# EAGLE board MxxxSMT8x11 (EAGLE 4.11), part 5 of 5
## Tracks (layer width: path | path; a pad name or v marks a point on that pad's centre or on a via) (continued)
T4  (via drill 0.61) (continued)
  Top 0.254: v196.85,149.61 197.87,149.61 E69.3 | E72.4 186.94,148.84 186.94,149.1 v187.96,149.1 188.21,149.35 189.48,150.62 v189.48,151.13 | E81.12 170.43,150.11 v171.45,150.11 173.74,150.11 E75.3 175.51,149.86 v176.53,149.86 | v158.75,153.67 157.23,153.67 155.19,151.64 155.19,147.57 157.23,147.57 E84.10 | v238,140.46 238,140.21 234.44,140.21 233.68,140.97 233.68,141.48 234.7,142.49 234.7,149.61 v233.68,149.61 232.66,149.61 E78.12 | v220.98,147.32 219.96,147.32 E65.10
  Bottom 0.254: v196.85,149.61 196.34,149.1 v187.96,149.1 187.71,149.1 177.29,149.1 v176.53,149.86 | v158.75,153.67 159.77,152.65 168.91,152.65 v171.45,150.11 | v238,140.46 239.27,141.73 242.57,141.73 U$12.T2 | v233.68,149.61 232.41,148.34 222,148.34 v220.98,147.32 220.73,147.57 219.96,147.57 219.96,148.59 217.17,151.38 216.92,151.38 215.9,152.4 210.57,152.4 210.31,152.15 194.06,152.15 193.04,151.13 v189.48,151.13
T5  (via drill 0.61)
  Top 0.254: v196.85,83.57 197.87,83.57 E90.3 | E93.4 186.94,82.8 186.94,83.06 v187.96,83.06 188.21,83.31 189.48,84.58 v189.48,85.09 | E102.12 170.43,84.07 v171.45,84.07 173.74,84.07 E96.3 175.51,83.82 v176.53,83.82 | v158.75,87.63 157.23,87.63 155.19,85.6 155.19,81.53 157.23,81.53 E105.10 | v238,74.42 238,74.17 234.44,74.17 233.68,74.93 233.68,75.44 234.7,76.45 234.7,83.57 v233.68,83.57 232.66,83.57 E99.12 | v220.98,81.28 219.96,81.28 E86.10
  Bottom 0.254: v196.85,83.57 196.34,83.06 v187.96,83.06 187.71,83.06 177.29,83.06 v176.53,83.82 | v158.75,87.63 159.77,86.61 168.91,86.61 v171.45,84.07 | v238,74.42 239.27,75.69 242.57,75.69 U$15.T2 | v233.68,83.57 232.41,82.3 222,82.3 v220.98,81.28 220.73,81.53 219.96,81.53 219.96,82.55 217.17,85.34 216.92,85.34 215.9,86.36 210.57,86.36 210.31,86.11 194.06,86.11 193.04,85.09 v189.48,85.09
T6  (via drill 0.61)
  Top 0.254: v196.85,17.53 197.87,17.53 E111.3 | E114.4 186.94,16.76 186.94,17.02 v187.96,17.02 188.21,17.27 189.48,18.54 v189.48,19.05 | E123.12 170.43,18.03 v171.45,18.03 173.74,18.03 E117.3 175.51,17.78 v176.53,17.78 | v158.75,21.59 157.23,21.59 155.19,19.56 155.19,15.49 157.23,15.49 E126.10 | v238,8.38 238,8.13 234.44,8.13 233.68,8.89 233.68,9.4 234.7,10.41 234.7,17.53 v233.68,17.53 232.66,17.53 E120.12 | v220.98,15.24 219.96,15.24 E107.10
  Bottom 0.254: v196.85,17.53 196.34,17.02 v187.96,17.02 187.71,17.02 177.29,17.02 v176.53,17.78 | v158.75,21.59 159.77,20.57 168.91,20.57 v171.45,18.03 | v238,8.38 239.27,9.65 242.57,9.65 U$18.T2 | v233.68,17.53 232.41,16.26 222,16.26 v220.98,15.24 220.73,15.49 219.96,15.49 219.96,16.51 217.17,19.3 216.92,19.3 215.9,20.32 210.57,20.32 210.31,20.07 194.06,20.07 193.04,19.05 v189.48,19.05
U1  (via drill 0.61)
  Top 0.254: v26.67,47.24 25.65,47.24 E3.10 | 14.73,53.34 13.97,54.1 U$1.U1 | 14.73,53.34 v20.07,48.01 | v100.33,43.43 99.31,43.43 E21.13 | v95.25,47.75 94.23,47.75 94.23,48.01 E18.6 | v53.09,52.83 53.09,44.7 52.32,44.7 E9.12 | v107.19,45.97 107.7,46.48 107.7,50.29 v98.55,59.44 | v64.26,59.44 62.48,57.66 R1.2 | 14.73,53.34 v18.54,57.15
  Bottom 0.254: v26.67,47.24 25.91,48.01 v20.07,48.01 | v95.25,47.75 96.01,47.75 v100.33,43.43 100.58,43.69 102.87,45.97 v107.19,45.97 | v53.09,52.83 57.15,56.9 60.45,56.9 R2.1 61.47,56.9 61.72,56.9 R1.2 | v98.55,59.44 97.03,60.96 75.18,60.96 73.66,59.44 v64.26,59.44 64.01,59.18 51.31,59.18 49.28,57.15 v18.54,57.15
U2  (via drill 0.61)
  Top 0.254: v59.69,45.97 58.67,45.97 E9.4 | v68.58,46.48 69.6,46.48 69.6,46.74 E12.5 | v103.12,50.55 103.89,49.78 E21.7 | v93.22,52.32 87.88,46.99 E18.10 86.11,46.74 85.09,46.74 84.33,45.97 82.8,45.97 E15.4 81.03,45.72 v80.01,45.72 | 29.46,50.04 29.46,48.51 25.65,48.51 E3.9 | 29.46,50.04 30.73,51.31 35.56,51.31 | 35.56,51.31 36.07,51.31 36.07,48.77 36.58,48.26 E6.9 | 29.46,50.04 24.38,55.12 17.53,55.12 v17.53,54.86 | v49.02,45.72 48.26,46.48 48.26,49.78 38.86,59.18 35.56,59.18 35.56,51.31
  Bottom 0.254: v103.12,50.55 100.33,53.34 94.23,53.34 v93.22,52.32 | v80.01,45.72 69.34,45.72 68.83,46.23 v68.58,46.48 60.2,46.48 v59.69,45.97 59.44,45.72 v49.02,45.72 | v17.53,54.86 13.97,54.86 U$1.U2
U3  (via drill 0.61)
  Top 0.254: v59.69,112.01 58.67,112.01 E27.4 | v68.58,112.52 69.6,112.52 69.6,112.78 E30.5 | v103.12,116.59 103.89,115.82 E42.7 | v93.22,118.36 87.88,113.03 E39.10 86.11,112.78 85.09,112.78 84.33,112.01 82.8,112.01 E33.4 81.03,111.76 v80.01,111.76 | 29.46,116.08 29.46,114.55 25.65,114.55 E36.9 | 29.46,116.08 30.73,117.35 35.56,117.35 | 35.56,117.35 36.07,117.35 36.07,114.81 36.58,114.3 E23.9 | 29.46,116.08 24.38,121.16 17.53,121.16 v17.53,120.9 | v49.02,111.76 48.26,112.52 48.26,115.82 38.86,125.22 35.56,125.22 35.56,117.35
  Bottom 0.254: v103.12,116.59 100.33,119.38 94.23,119.38 v93.22,118.36 | v80.01,111.76 69.34,111.76 68.83,112.27 v68.58,112.52 60.2,112.52 v59.69,112.01 59.44,111.76 v49.02,111.76 | v17.53,120.9 13.97,120.9 U$6.U2
U4  (via drill 0.61)
  Top 0.254: v26.67,113.28 25.65,113.28 E36.10 | 14.73,119.38 13.97,120.14 U$6.U1 | 14.73,119.38 v20.07,114.05 | v100.33,109.47 99.31,109.47 E42.13 | v95.25,113.79 94.23,113.79 94.23,114.05 E39.6 | v53.09,118.87 53.09,110.74 52.32,110.74 E27.12 | v107.19,112.01 107.7,112.52 107.7,116.33 v98.55,125.48 | v64.26,125.48 62.48,123.7 R5.2 | 14.73,119.38 v18.54,123.19
  Bottom 0.254: v26.67,113.28 25.91,114.05 v20.07,114.05 | v95.25,113.79 96.01,113.79 v100.33,109.47 100.58,109.73 102.87,112.01 v107.19,112.01 | v53.09,118.87 57.15,122.94 60.45,122.94 R6.1 61.47,122.94 61.72,122.94 R5.2 | v98.55,125.48 97.03,127 75.18,127 73.66,125.48 v64.26,125.48 64.01,125.22 51.31,125.22 49.28,123.19 v18.54,123.19
U5  (via drill 0.61)
  Top 0.254: v59.69,178.05 58.67,178.05 E48.4 | v68.58,178.56 69.6,178.56 69.6,178.82 E51.5 | v103.12,182.63 103.89,181.86 E63.7 | v93.22,184.4 87.88,179.07 E60.10 86.11,178.82 85.09,178.82 84.33,178.05 82.8,178.05 E54.4 81.03,177.8 v80.01,177.8 | 29.46,182.12 29.46,180.59 25.65,180.59 E57.9 | 29.46,182.12 30.73,183.39 35.56,183.39 | 35.56,183.39 36.07,183.39 36.07,180.85 36.58,180.34 E44.9 | 29.46,182.12 24.38,187.2 17.53,187.2 v17.53,186.94 | v49.02,177.8 48.26,178.56 48.26,181.86 38.86,191.26 35.56,191.26 35.56,183.39
  Bottom 0.254: v103.12,182.63 100.33,185.42 94.23,185.42 v93.22,184.4 | v80.01,177.8 69.34,177.8 68.83,178.31 v68.58,178.56 60.2,178.56 v59.69,178.05 59.44,177.8 v49.02,177.8 | v17.53,186.94 13.97,186.94 U$9.U2
U6  (via drill 0.61)
  Top 0.254: v26.67,179.32 25.65,179.32 E57.10 | 14.73,185.42 13.97,186.18 U$9.U1 | 14.73,185.42 v20.07,180.09 | v100.33,175.51 99.31,175.51 E63.13 | v95.25,179.83 94.23,179.83 94.23,180.09 E60.6 | v53.09,184.91 53.09,176.78 52.32,176.78 E48.12 | v107.19,178.05 107.7,178.56 107.7,182.37 v98.55,191.52 | v64.26,191.52 62.48,189.74 R9.2 | v18.54,189.23 14.73,185.42
  Bottom 0.254: v26.67,179.32 25.91,180.09 v20.07,180.09 | v95.25,179.83 96.01,179.83 v100.33,175.51 100.58,175.77 102.87,178.05 v107.19,178.05 | v53.09,184.91 57.15,188.98 60.45,188.98 R10.1 61.47,188.98 61.72,188.98 R9.2 | v98.55,191.52 97.03,193.04 75.18,193.04 73.66,191.52 v64.26,191.52 64.01,191.26 51.31,191.26 49.28,189.23 v18.54,189.23
U7  (via drill 0.61)
  Top 0.254: v196.85,148.34 197.87,148.34 E69.4 | v187.96,147.83 186.94,147.83 186.94,147.57 E72.5 | v153.42,143.76 152.65,144.53 E84.7 | v163.32,141.99 168.66,147.32 E81.10 170.43,147.57 171.45,147.57 172.21,148.34 173.74,148.34 E75.4 175.51,148.59 v176.53,148.59 | 227.08,144.27 227.08,145.8 230.89,145.8 E78.9 | 227.08,144.27 225.81,143 220.98,143 | 220.98,143 220.47,143 220.47,145.54 219.96,146.05 E65.9 | 227.08,144.27 232.16,139.19 239.01,139.19 v239.01,139.45 | v207.52,148.59 208.28,147.83 208.28,144.53 217.68,135.13 220.98,135.13 220.98,143
  Bottom 0.254: v153.42,143.76 156.21,140.97 162.31,140.97 v163.32,141.99 | v176.53,148.59 187.2,148.59 187.71,148.08 v187.96,147.83 196.34,147.83 v196.85,148.34 197.1,148.59 v207.52,148.59 | v239.01,139.45 242.57,139.45 U$12.U2
U8  (via drill 0.61)
  Top 0.254: v229.87,147.07 230.89,147.07 E78.10 | 241.81,140.97 242.57,140.21 U$12.U1 | 241.81,140.97 v236.47,146.3 | v156.21,150.88 157.23,150.88 E84.13 | v161.29,146.56 162.31,146.56 162.31,146.3 E81.6 | v203.45,141.48 203.45,149.61 204.22,149.61 E69.12 | v149.35,148.34 148.84,147.83 148.84,144.02 v157.99,134.87 | v192.28,134.87 194.06,136.65 R13.2 | v238,137.16 241.81,140.97
  Bottom 0.254: v229.87,147.07 230.63,146.3 v236.47,146.3 | v161.29,146.56 160.53,146.56 v156.21,150.88 155.96,150.62 153.67,148.34 v149.35,148.34 | v203.45,141.48 199.39,137.41 196.09,137.41 R14.1 195.07,137.41 194.82,137.41 R13.2 | v157.99,134.87 159.51,133.35 181.36,133.35 182.88,134.87 v192.28,134.87 192.53,135.13 205.23,135.13 207.26,137.16 v238,137.16
U9  (via drill 0.61)
  Top 0.254: v196.85,82.3 197.87,82.3 E90.4 | v187.96,81.79 186.94,81.79 186.94,81.53 E93.5 | v153.42,77.72 152.65,78.49 E105.7 | v163.32,75.95 168.66,81.28 E102.10 170.43,81.53 171.45,81.53 172.21,82.3 173.74,82.3 E96.4 175.51,82.55 v176.53,82.55 | 227.08,78.23 227.08,79.76 230.89,79.76 E99.9 | 227.08,78.23 225.81,76.96 220.98,76.96 | 220.98,76.96 220.47,76.96 220.47,79.5 219.96,80.01 E86.9 | 227.08,78.23 232.16,73.15 239.01,73.15 v239.01,73.41 | v207.52,82.55 208.28,81.79 208.28,78.49 217.68,69.09 220.98,69.09 220.98,76.96
  Bottom 0.254: v153.42,77.72 156.21,74.93 162.31,74.93 v163.32,75.95 | v176.53,82.55 187.2,82.55 187.71,82.04 v187.96,81.79 196.34,81.79 v196.85,82.3 197.1,82.55 v207.52,82.55 | v239.01,73.41 242.57,73.41 U$15.U2
U10  (via drill 0.61)
  Top 0.254: v229.87,81.03 230.89,81.03 E99.10 | 241.81,74.93 242.57,74.17 U$15.U1 | 241.81,74.93 v236.47,80.26 | v156.21,84.84 157.23,84.84 E105.13 | v161.29,80.52 162.31,80.52 162.31,80.26 E102.6 | v203.45,75.44 203.45,83.57 204.22,83.57 E90.12 | v149.35,82.3 148.84,81.79 148.84,77.98 v157.99,68.83 | v192.28,68.83 194.06,70.61 R17.2 | v238,71.12 241.81,74.93
  Bottom 0.254: v229.87,81.03 230.63,80.26 v236.47,80.26 | v161.29,80.52 160.53,80.52 v156.21,84.84 155.96,84.58 153.67,82.3 v149.35,82.3 | v203.45,75.44 199.39,71.37 196.09,71.37 R18.1 195.07,71.37 194.82,71.37 R17.2 | v157.99,68.83 159.51,67.31 181.36,67.31 182.88,68.83 v192.28,68.83 192.53,69.09 205.23,69.09 207.26,71.12 v238,71.12
U11  (via drill 0.61)
  Top 0.254: v196.85,16.26 197.87,16.26 E111.4 | v187.96,15.75 186.94,15.75 186.94,15.49 E114.5 | v153.42,11.68 152.65,12.45 E126.7 | v163.32,9.91 168.66,15.24 E123.10 170.43,15.49 171.45,15.49 172.21,16.26 173.74,16.26 E117.4 175.51,16.51 v176.53,16.51 | 227.08,12.19 227.08,13.72 230.89,13.72 E120.9 | 227.08,12.19 225.81,10.92 220.98,10.92 | 220.98,10.92 220.47,10.92 220.47,13.46 219.96,13.97 E107.9 | 227.08,12.19 232.16,7.11 239.01,7.11 v239.01,7.37 | v207.52,16.51 208.28,15.75 208.28,12.45 217.68,3.05 220.98,3.05 220.98,10.92
  Bottom 0.254: v153.42,11.68 156.21,8.89 162.31,8.89 v163.32,9.91 | v176.53,16.51 187.2,16.51 187.71,16 v187.96,15.75 196.34,15.75 v196.85,16.26 197.1,16.51 v207.52,16.51 | v239.01,7.37 242.57,7.37 U$18.U2
U12  (via drill 0.61)
  Top 0.254: v229.87,14.99 230.89,14.99 E120.10 | 241.81,8.89 242.57,8.13 U$18.U1 | 241.81,8.89 v236.47,14.22 | v156.21,18.8 157.23,18.8 E126.13 | v161.29,14.48 162.31,14.48 162.31,14.22 E123.6 | v203.45,9.4 203.45,17.53 204.22,17.53 E111.12 | v149.35,16.26 148.84,15.75 148.84,11.94 v157.99,2.79 | v192.28,2.79 194.06,4.57 R21.2 | v238,5.08 241.81,8.89
  Bottom 0.254: v229.87,14.99 230.63,14.22 v236.47,14.22 | v161.29,14.48 160.53,14.48 v156.21,18.8 155.96,18.54 153.67,16.26 v149.35,16.26 | v203.45,9.4 199.39,5.33 196.09,5.33 R22.1 195.07,5.33 194.82,5.33 R21.2 | v157.99,2.79 159.51,1.27 181.36,1.27 182.88,2.79 v192.28,2.79 192.53,3.05 205.23,3.05 207.26,5.08 v238,5.08
V1  (via drill 0.61)
  Top 0.254: v22.86,50.8 22.86,45.97 23.88,45.97 E3.11 | E9.6 58.67,48.51 60.45,48.51 60.45,54.36 R4.1 | v84.33,53.09 84.33,51.56 86.11,49.78 E18.8 87.88,49.78 v89.92,51.82 | v96.77,50.29 96.77,49.78 97.54,49.78 E21.8 | v14.99,56.13 13.97,57.15 U$1.V1
  Bottom 0.254: 59.44,53.34 60.45,54.36 R4.1 61.47,54.36 61.72,54.36 R3.2 | 59.44,53.34 57.91,51.82 23.88,51.82 v22.86,50.8 22.61,51.05 17.78,55.88 15.24,55.88 v14.99,56.13 | v84.33,53.09 84.07,53.34 59.44,53.34 | v96.77,50.29 96.27,50.8 92.2,50.8 91.19,51.82 v89.92,51.82
V2  (via drill 0.61)
  Top 0.254: E21.9 97.54,48.26 95.25,50.55 95.25,53.34 92.96,53.34 88.65,49.02 88.65,48.51 87.88,48.51 E18.9 86.11,48.26 83.31,51.05 83.31,56.39 79.76,56.39 78.23,54.86 78.23,51.56 76.45,49.78 E15.8 74.68,49.28 73.66,49.28 v73.66,49.02 | v23.88,54.1 23.88,49.78 E3.8 | v36.58,54.1 36.58,49.78 E6.8 | E9.5 56.9,47.24 55.63,47.24 55.63,48.51 54.1,50.04 54.1,53.34 v51.82,55.63 52.07,55.88 62.48,55.88 66.8,51.56 v66.8,49.02 66.8,48.51 69.6,48.51 E12.6
  Bottom 0.254: U$1.V2 13.97,57.15 17.27,57.15 18.29,56.13 21.84,56.13 v23.88,54.1 24.13,54.1 v36.58,54.1 36.83,54.36 38.35,55.88 51.56,55.88 v51.82,55.63 | v66.8,49.02 v73.66,49.02
V3  (via drill 0.61)
  Top 0.254: v22.86,116.84 22.86,112.01 23.88,112.01 E36.11 | E27.6 58.67,114.55 60.45,114.55 60.45,120.4 R7.1 | v84.33,119.13 84.33,117.6 86.11,115.82 E39.8 87.88,115.82 v89.92,117.86 | v96.77,116.33 96.77,115.82 97.54,115.82 E42.8 | v14.99,122.17 13.97,123.19 U$6.V1
  Bottom 0.254: 59.44,119.38 60.45,120.4 R7.1 61.47,120.4 61.72,120.4 R8.2 | 59.44,119.38 57.91,117.86 23.88,117.86 v22.86,116.84 22.61,117.09 17.78,121.92 15.24,121.92 v14.99,122.17 | v84.33,119.13 84.07,119.38 59.44,119.38 | v96.77,116.33 96.27,116.84 92.2,116.84 91.19,117.86 v89.92,117.86
V4  (via drill 0.61)
  Top 0.254: E42.9 97.54,114.3 95.25,116.59 95.25,119.38 92.96,119.38 88.65,115.06 88.65,114.55 87.88,114.55 E39.9 86.11,114.3 83.31,117.09 83.31,122.43 79.76,122.43 78.23,120.9 78.23,117.6 76.45,115.82 E33.8 74.68,115.32 73.66,115.32 v73.66,115.06 | v23.88,120.14 23.88,115.82 E36.8 | v36.58,120.14 36.58,115.82 E23.8 | E27.5 56.9,113.28 55.63,113.28 55.63,114.55 54.1,116.08 54.1,119.38 v51.82,121.67 52.07,121.92 62.48,121.92 66.8,117.6 v66.8,115.06 66.8,114.55 69.6,114.55 E30.6
  Bottom 0.254: U$6.V2 13.97,123.19 17.27,123.19 18.29,122.17 21.84,122.17 v23.88,120.14 24.13,120.14 v36.58,120.14 36.83,120.4 38.35,121.92 51.56,121.92 v51.82,121.67 | v66.8,115.06 v73.66,115.06
V5  (via drill 0.61)
  Top 0.254: v22.86,182.88 22.86,178.05 23.88,178.05 E57.11 | E48.6 58.67,180.59 60.45,180.59 60.45,186.44 R11.1 | v84.33,185.17 84.33,183.64 86.11,181.86 E60.8 87.88,181.86 v89.92,183.9 | v96.77,182.37 96.77,181.86 97.54,181.86 E63.8 | v14.99,188.21 13.97,189.23 U$9.V1
  Bottom 0.254: 59.44,185.42 60.45,186.44 R11.1 61.47,186.44 61.72,186.44 R12.2 | 59.44,185.42 57.91,183.9 23.88,183.9 v22.86,182.88 22.61,183.13 17.78,187.96 15.24,187.96 v14.99,188.21 | v84.33,185.17 84.07,185.42 59.44,185.42 | v96.77,182.37 96.27,182.88 92.2,182.88 91.19,183.9 v89.92,183.9
V6  (via drill 0.61)
  Top 0.254: E63.9 97.54,180.34 95.25,182.63 95.25,185.42 92.96,185.42 88.65,181.1 88.65,180.59 87.88,180.59 E60.9 86.11,180.34 83.31,183.13 83.31,188.47 79.76,188.47 78.23,186.94 78.23,183.64 76.45,181.86 E54.8 74.68,181.36 73.66,181.36 v73.66,181.1 | v23.88,186.18 23.88,181.86 E57.8 | v36.58,186.18 36.58,181.86 E44.8 | E48.5 56.9,179.32 55.63,179.32 55.63,180.59 54.1,182.12 54.1,185.42 v51.82,187.71 52.07,187.96 62.48,187.96 66.8,183.64 v66.8,181.1 66.8,180.59 69.6,180.59 E51.6
  Bottom 0.254: U$9.V2 13.97,189.23 17.27,189.23 18.29,188.21 21.84,188.21 v23.88,186.18 24.13,186.18 v36.58,186.18 36.83,186.44 38.35,187.96 51.56,187.96 v51.82,187.71 | v73.66,181.1 v66.8,181.1
V7  (via drill 0.61)
  Top 0.254: v233.68,143.51 233.68,148.34 232.66,148.34 E78.11 | E69.6 197.87,145.8 196.09,145.8 196.09,139.95 R15.1 | v172.21,141.22 172.21,142.75 170.43,144.53 E81.8 168.66,144.53 v166.62,142.49 | v159.77,144.02 159.77,144.53 159,144.53 E84.8 | v241.55,138.18 242.57,137.16 U$12.V1
  Bottom 0.254: 197.1,140.97 196.09,139.95 R15.1 195.07,139.95 194.82,139.95 R16.2 | 197.1,140.97 198.63,142.49 232.66,142.49 v233.68,143.51 233.93,143.26 238.76,138.43 241.3,138.43 v241.55,138.18 | v172.21,141.22 172.47,140.97 197.1,140.97 | v159.77,144.02 160.27,143.51 164.34,143.51 165.35,142.49 v166.62,142.49
V8  (via drill 0.61)
  Top 0.254: E84.9 159,146.05 161.29,143.76 161.29,140.97 163.58,140.97 167.89,145.29 167.89,145.8 168.66,145.8 E81.9 170.43,146.05 173.23,143.26 173.23,137.92 176.78,137.92 178.31,139.45 178.31,142.75 180.09,144.53 E75.8 181.86,145.03 182.88,145.03 v182.88,145.29 | v232.66,140.21 232.66,144.53 E78.8 | v219.96,140.21 219.96,144.53 E65.8 | E69.5 199.64,147.07 200.91,147.07 200.91,145.8 202.44,144.27 202.44,140.97 v204.72,138.68 204.47,138.43 194.06,138.43 189.74,142.75 v189.74,145.29 189.74,145.8 186.94,145.8 E72.6
  Bottom 0.254: U$12.V2 242.57,137.16 239.27,137.16 238.25,138.18 234.7,138.18 v232.66,140.21 232.41,140.21 v219.96,140.21 219.71,139.95 218.19,138.43 204.98,138.43 v204.72,138.68 | v182.88,145.29 v189.74,145.29
V9  (via drill 0.61)
  Top 0.254: v233.68,77.47 233.68,82.3 232.66,82.3 E99.11 | E90.6 197.87,79.76 196.09,79.76 196.09,73.91 R19.1 | v172.21,75.18 172.21,76.71 170.43,78.49 E102.8 168.66,78.49 v166.62,76.45 | v159.77,77.98 159.77,78.49 159,78.49 E105.8 | v241.55,72.14 242.57,71.12 U$15.V1
  Bottom 0.254: 197.1,74.93 196.09,73.91 R19.1 195.07,73.91 194.82,73.91 R20.2 | 197.1,74.93 198.63,76.45 232.66,76.45 v233.68,77.47 233.93,77.22 238.76,72.39 241.3,72.39 v241.55,72.14 | v172.21,75.18 172.47,74.93 197.1,74.93 | v159.77,77.98 160.27,77.47 164.34,77.47 165.35,76.45 v166.62,76.45
V10  (via drill 0.61)
  Top 0.254: E105.9 159,80.01 161.29,77.72 161.29,74.93 163.58,74.93 167.89,79.25 167.89,79.76 168.66,79.76 E102.9 170.43,80.01 173.23,77.22 173.23,71.88 176.78,71.88 178.31,73.41 178.31,76.71 180.09,78.49 E96.8 181.86,78.99 182.88,78.99 v182.88,79.25 | v232.66,74.17 232.66,78.49 E99.8 | v219.96,74.17 219.96,78.49 E86.8 | E90.5 199.64,81.03 200.91,81.03 200.91,79.76 202.44,78.23 202.44,74.93 v204.72,72.64 204.47,72.39 194.06,72.39 189.74,76.71 v189.74,79.25 189.74,79.76 186.94,79.76 E93.6
  Bottom 0.254: U$15.V2 242.57,71.12 239.27,71.12 238.25,72.14 234.7,72.14 v232.66,74.17 232.41,74.17 v219.96,74.17 219.71,73.91 218.19,72.39 204.98,72.39 v204.72,72.64 | v182.88,79.25 v189.74,79.25
V11  (via drill 0.61)
  Top 0.254: v233.68,11.43 233.68,16.26 232.66,16.26 E120.11 | E111.6 197.87,13.72 196.09,13.72 196.09,7.87 R23.1 | v172.21,9.14 172.21,10.67 170.43,12.45 E123.8 168.66,12.45 v166.62,10.41 | v159.77,11.94 159.77,12.45 159,12.45 E126.8 | v241.55,6.1 242.57,5.08 U$18.V1
  Bottom 0.254: 197.1,8.89 196.09,7.87 R23.1 195.07,7.87 194.82,7.87 R24.2 | 197.1,8.89 198.63,10.41 232.66,10.41 v233.68,11.43 233.93,11.18 238.76,6.35 241.3,6.35 v241.55,6.1 | v172.21,9.14 172.47,8.89 197.1,8.89 | v159.77,11.94 160.27,11.43 164.34,11.43 165.35,10.41 v166.62,10.41
V12  (via drill 0.61)
  Top 0.254: E126.9 159,13.97 161.29,11.68 161.29,8.89 163.58,8.89 167.89,13.21 167.89,13.72 168.66,13.72 E123.9 170.43,13.97 173.23,11.18 173.23,5.84 176.78,5.84 178.31,7.37 178.31,10.67 180.09,12.45 E117.8 181.86,12.95 182.88,12.95 v182.88,13.21 | v232.66,8.13 232.66,12.45 E120.8 | v219.96,8.13 219.96,12.45 E107.8 | E111.5 199.64,14.99 200.91,14.99 200.91,13.72 202.44,12.19 202.44,8.89 v204.72,6.6 204.47,6.35 194.06,6.35 189.74,10.67 v189.74,13.21 189.74,13.72 186.94,13.72 E114.6
  Bottom 0.254: U$18.V2 242.57,5.08 239.27,5.08 238.25,6.1 234.7,6.1 v232.66,8.13 232.41,8.13 v219.96,8.13 219.71,7.87 218.19,6.35 204.98,6.35 v204.72,6.6 | v182.88,13.21 v189.74,13.21
VCC
  Top 0.381: E21.4 103.89,45.47 103.12,45.47 103.12,40.64 103.89,39.88 C21.1 | E15.14 75.95,41.66 75.95,39.88 C15.1 | E18.14 87.38,41.66 87.38,39.88 C18.1 | E3.14 25.15,41.66 25.15,39.88 C3.1 25.65,38.86 26.42,38.1 26.42,25.91 25.65,25.15 E2.14 25.15,25.15 25.15,23.37 C2.1 | E6.14 37.85,41.66 37.85,39.88 C6.1 | C9.1 51.82,39.88 51.82,41.66 E9.14 50.55,41.91 50.04,42.42 50.04,53.59 50.55,54.1 R4.2 | E12.14 64.52,41.66 64.52,39.88 C12.1 | 104.78,23.24 104.65,23.11 C20.1 | 104.78,23.24 106.17,24.64 106.17,28.96 105.66,28.96 E20.4 | E14.14 75.95,25.15 75.95,23.37 C14.1 | E17.14 87.38,25.15 87.38,23.37 C17.1 | E11.14 64.52,25.15 64.52,23.37 C11.1 | E8.14 51.82,25.15 51.82,23.37 C8.1 | E5.14 37.85,25.15 37.85,23.37 C5.1 | C19.1 104.65,6.6 106.17,8.13 106.17,12.45 105.66,12.45 E19.4 105.66,12.7 106.93,13.97 106.93,21.08 104.9,23.11 104.78,23.24 | E13.14 75.95,8.64 75.95,6.86 C13.1 | E16.14 87.38,8.64 87.38,6.86 C16.1 | E10.14 64.52,8.64 64.52,6.86 C10.1 | E7.14 51.82,8.64 51.82,6.86 C7.1 | E4.14 37.85,8.64 37.85,6.86 C4.1 | E1.14 25.15,8.64 25.15,6.86 C1.1
  Bottom 0.381: 86.23,38.23 87.12,39.12 C18.1 | 86.23,38.23 86.11,38.1 77.72,38.1 76.71,39.12 C15.1 75.69,39.37 71.63,39.37 70.36,38.1 63.5,38.1 63.37,38.23 | C21.1 103.63,39.12 102.62,38.1 86.36,38.1 86.23,38.23 | C3.1 25.91,39.12 26.92,38.1 32.26,38.1 33.27,39.12 37.59,39.12 C6.1 38.61,39.12 39.62,38.1 43.69,38.1 44.7,39.12 51.56,39.12 C9.1 52.58,39.12 53.09,38.61 56.13,38.61 56.64,38.1 63.25,38.1 63.37,38.23 | R4.2 51.31,54.61 52.32,54.61 52.83,55.12 52.83,56.64 51.05,56.64 R2.2 | 63.37,38.23 64.26,39.12 C12.1 | C20.1 103.63,22.61 101.85,20.83 89.92,20.83 88.14,22.61 C17.1 87.12,22.61 86.11,21.59 77.72,21.59 76.71,22.61 C14.1 75.69,22.61 74.68,21.59 69.34,21.59 68.33,22.61 65.28,22.61 C11.1 64.26,22.61 64.01,22.35 58.42,22.35 57.66,21.59 50.8,21.59 50.67,21.72 | 36.7,21.72 37.59,22.61 C5.1 | 36.7,21.72 36.58,21.59 26.92,21.59 25.91,22.61 C2.1 | 50.67,21.72 50.55,21.59 36.83,21.59 36.7,21.72 | 50.67,21.72 51.56,22.61 C8.1 | 86.23,5.21 87.12,6.1 C16.1 | 86.23,5.21 86.11,5.08 77.72,5.08 76.71,6.1 C13.1 75.69,6.35 71.63,6.35 70.36,5.08 63.5,5.08 63.37,5.21 | C19.1 103.63,6.1 102.62,5.08 86.36,5.08 86.23,5.21 | U$1.A2 13.97,5.08 15.24,6.35 24.89,6.35 C1.1 25.91,6.1 26.92,5.08 36.58,5.08 36.7,5.21 | 36.7,5.21 37.59,6.1 C4.1 | 50.67,5.21 50.55,5.08 36.83,5.08 36.7,5.21 | 50.67,5.21 51.56,6.1 C7.1 | 63.37,5.21 63.25,5.08 50.8,5.08 50.67,5.21 | 63.37,5.21 64.26,6.1 C10.1
VCC1
  Top 0.381: E42.4 103.89,111.51 103.12,111.51 103.12,106.68 103.89,105.92 C42.1 | E33.14 75.95,107.7 75.95,105.92 C35.1 | E39.14 87.38,107.7 87.38,105.92 C39.1 | E36.14 25.15,107.7 25.15,105.92 C24.1 25.65,104.9 26.42,104.14 26.42,91.95 25.65,91.19 E35.14 25.15,91.19 25.15,89.41 C23.1 | E23.14 37.85,107.7 37.85,105.92 C36.1 | C29.1 51.82,105.92 51.82,107.7 E27.14 50.55,107.95 50.04,108.46 50.04,119.63 50.55,120.14 R7.2 | E30.14 64.52,107.7 64.52,105.92 C32.1 | 104.78,89.28 104.65,89.15 C41.1 | 104.78,89.28 106.17,90.68 106.17,95 105.66,95 E41.4 | E32.14 75.95,91.19 75.95,89.41 C34.1 | E38.14 87.38,91.19 87.38,89.41 C38.1 | E29.14 64.52,91.19 64.52,89.41 C31.1 | E26.14 51.82,91.19 51.82,89.41 C28.1 | E24.14 37.85,91.19 37.85,89.41 C26.1 | C40.1 104.65,72.64 106.17,74.17 106.17,78.49 105.66,78.49 E40.4 105.66,78.74 106.93,80.01 106.93,87.12 104.9,89.15 104.78,89.28 | E31.14 75.95,74.68 75.95,72.9 C33.1 | E37.14 87.38,74.68 87.38,72.9 C37.1 | E28.14 64.52,74.68 64.52,72.9 C30.1 | E25.14 51.82,74.68 51.82,72.9 C27.1 | E22.14 37.85,74.68 37.85,72.9 C25.1 | E34.14 25.15,74.68 25.15,72.9 C22.1
  Bottom 0.381: 86.23,104.27 87.12,105.16 C39.1 | 86.23,104.27 86.11,104.14 77.72,104.14 76.71,105.16 C35.1 75.69,105.41 71.63,105.41 70.36,104.14 63.5,104.14 63.37,104.27 | C42.1 103.63,105.16 102.62,104.14 86.36,104.14 86.23,104.27 | C24.1 25.91,105.16 26.92,104.14 32.26,104.14 33.27,105.16 37.59,105.16 C36.1 38.61,105.16 39.62,104.14 43.69,104.14 44.7,105.16 51.56,105.16 C29.1 52.58,105.16 53.09,104.65 56.13,104.65 56.64,104.14 63.25,104.14 63.37,104.27 | R7.2 51.31,120.65 52.32,120.65 52.83,121.16 52.83,122.68 51.05,122.68 R6.2 | 63.37,104.27 64.26,105.16 C32.1 | C41.1 103.63,88.65 101.85,86.87 89.92,86.87 88.14,88.65 C38.1 87.12,88.65 86.11,87.63 77.72,87.63 76.71,88.65 C34.1 75.69,88.65 74.68,87.63 69.34,87.63 68.33,88.65 65.28,88.65 C31.1 64.26,88.65 64.01,88.39 58.42,88.39 57.66,87.63 50.8,87.63 50.67,87.76 | 36.7,87.76 37.59,88.65 C26.1 | 36.7,87.76 36.58,87.63 26.92,87.63 25.91,88.65 C23.1 | 50.67,87.76 50.55,87.63 36.83,87.63 36.7,87.76 | 50.67,87.76 51.56,88.65 C28.1 | 86.23,71.25 87.12,72.14 C37.1 | 86.23,71.25 86.11,71.12 77.72,71.12 76.71,72.14 C33.1 75.69,72.39 71.63,72.39 70.36,71.12 63.5,71.12 63.37,71.25 | C40.1 103.63,72.14 102.62,71.12 86.36,71.12 86.23,71.25 | U$6.A2 13.97,71.12 15.24,72.39 24.89,72.39 C22.1 25.91,72.14 26.92,71.12 36.58,71.12 36.7,71.25 | 36.7,71.25 37.59,72.14 C25.1 | 50.67,71.25 50.55,71.12 36.83,71.12 36.7,71.25 | 50.67,71.25 51.56,72.14 C27.1 | 63.37,71.25 63.25,71.12 50.8,71.12 50.67,71.25 | 63.37,71.25 64.26,72.14 C30.1
VCC2
  Top 0.381: E63.4 103.89,177.55 103.12,177.55 103.12,172.72 103.89,171.96 C63.1 | E54.14 75.95,173.74 75.95,171.96 C56.1 | E60.14 87.38,173.74 87.38,171.96 C60.1 | E57.14 25.15,173.74 25.15,171.96 C45.1 25.65,170.94 26.42,170.18 26.42,157.99 25.65,157.23 E56.14 25.15,157.23 25.15,155.45 C44.1 | E44.14 37.85,173.74 37.85,171.96 C57.1 | C50.1 51.82,171.96 51.82,173.74 E48.14 50.55,173.99 50.04,174.5 50.04,185.67 50.55,186.18 R11.2 | E51.14 64.52,173.74 64.52,171.96 C53.1 | 104.78,155.32 104.65,155.19 C62.1 | 104.78,155.32 106.17,156.72 106.17,161.04 105.66,161.04 E62.4 | E53.14 75.95,157.23 75.95,155.45 C55.1 | E59.14 87.38,157.23 87.38,155.45 C59.1 | E50.14 64.52,157.23 64.52,155.45 C52.1 | E47.14 51.82,157.23 51.82,155.45 C49.1 | E45.14 37.85,157.23 37.85,155.45 C47.1 | C61.1 104.65,138.68 106.17,140.21 106.17,144.53 105.66,144.53 E61.4 105.66,144.78 106.93,146.05 106.93,153.16 104.9,155.19 104.78,155.32 | E52.14 75.95,140.72 75.95,138.94 C54.1 | E58.14 87.38,140.72 87.38,138.94 C58.1 | E49.14 64.52,140.72 64.52,138.94 C51.1 | E46.14 51.82,140.72 51.82,138.94 C48.1 | E43.14 37.85,140.72 37.85,138.94 C46.1 | E55.14 25.15,140.72 25.15,138.94 C43.1
  Bottom 0.381: 86.23,170.31 87.12,171.2 C60.1 | 86.23,170.31 86.11,170.18 77.72,170.18 76.71,171.2 C56.1 75.69,171.45 71.63,171.45 70.36,170.18 63.5,170.18 63.37,170.31 | C63.1 103.63,171.2 102.62,170.18 86.36,170.18 86.23,170.31 | C45.1 25.91,171.2 26.92,170.18 32.26,170.18 33.27,171.2 37.59,171.2 C57.1 38.61,171.2 39.62,170.18 43.69,170.18 44.7,171.2 51.56,171.2 C50.1 52.58,171.2 53.09,170.69 56.13,170.69 56.64,170.18 63.25,170.18 63.37,170.31 | R11.2 51.31,186.69 52.32,186.69 52.83,187.2 52.83,188.72 51.05,188.72 R10.2 | 63.37,170.31 64.26,171.2 C53.1 | C62.1 103.63,154.69 101.85,152.91 89.92,152.91 88.14,154.69 C59.1 87.12,154.69 86.11,153.67 77.72,153.67 76.71,154.69 C55.1 75.69,154.69 74.68,153.67 69.34,153.67 68.33,154.69 65.28,154.69 C52.1 64.26,154.69 64.01,154.43 58.42,154.43 57.66,153.67 50.8,153.67 50.67,153.8 | 36.7,153.8 37.59,154.69 C47.1 | 36.7,153.8 36.58,153.67 26.92,153.67 25.91,154.69 C44.1 | 50.67,153.8 50.55,153.67 36.83,153.67 36.7,153.8 | 50.67,153.8 51.56,154.69 C49.1 | 86.23,137.29 87.12,138.18 C58.1 | 86.23,137.29 86.11,137.16 77.72,137.16 76.71,138.18 C54.1 75.69,138.43 71.63,138.43 70.36,137.16 63.5,137.16 63.37,137.29 | C61.1 103.63,138.18 102.62,137.16 86.36,137.16 86.23,137.29 | U$9.A2 13.97,137.16 15.24,138.43 24.89,138.43 C43.1 25.91,138.18 26.92,137.16 36.58,137.16 36.7,137.29 | 36.7,137.29 37.59,138.18 C46.1 | 50.67,137.29 50.55,137.16 36.83,137.16 36.7,137.29 | 50.67,137.29 51.56,138.18 C48.1 | 63.37,137.29 63.25,137.16 50.8,137.16 50.67,137.29 | 63.37,137.29 64.26,138.18 C51.1
VCC3
  Top 0.381: E84.4 152.65,148.84 153.42,148.84 153.42,153.67 152.65,154.43 C84.1 | E75.14 180.59,152.65 180.59,154.43 C77.1 | E81.14 169.16,152.65 169.16,154.43 C81.1 | E78.14 231.39,152.65 231.39,154.43 C66.1 230.89,155.45 230.12,156.21 230.12,168.4 230.89,169.16 E77.14 231.39,169.16 231.39,170.94 C65.1 | E65.14 218.69,152.65 218.69,154.43 C78.1 | C71.1 204.72,154.43 204.72,152.65 E69.14 205.99,152.4 206.5,151.89 206.5,140.72 205.99,140.21 R15.2 | E72.14 192.02,152.65 192.02,154.43 C74.1 | 151.77,171.07 151.89,171.2 C83.1 | 151.77,171.07 150.37,169.67 150.37,165.35 150.88,165.35 E83.4 | E74.14 180.59,169.16 180.59,170.94 C76.1 | E80.14 169.16,169.16 169.16,170.94 C80.1 | E71.14 192.02,169.16 192.02,170.94 C73.1 | E68.14 204.72,169.16 204.72,170.94 C70.1 | E66.14 218.69,169.16 218.69,170.94 C68.1 | C82.1 151.89,187.71 150.37,186.18 150.37,181.86 150.88,181.86 E82.4 150.88,181.61 149.61,180.34 149.61,173.23 151.64,171.2 151.77,171.07 | E73.14 180.59,185.67 180.59,187.45 C75.1 | E79.14 169.16,185.67 169.16,187.45 C79.1 | E70.14 192.02,185.67 192.02,187.45 C72.1 | E67.14 204.72,185.67 204.72,187.45 C69.1 | E64.14 218.69,185.67 218.69,187.45 C67.1 | E76.14 231.39,185.67 231.39,187.45 C64.1
  Bottom 0.381: 170.31,156.08 169.42,155.19 C81.1 | 170.31,156.08 170.43,156.21 178.82,156.21 179.83,155.19 C77.1 180.85,154.94 184.91,154.94 186.18,156.21 193.04,156.21 193.17,156.08 | C84.1 152.91,155.19 153.92,156.21 170.18,156.21 170.31,156.08 | C66.1 230.63,155.19 229.62,156.21 224.28,156.21 223.27,155.19 218.95,155.19 C78.1 217.93,155.19 216.92,156.21 212.85,156.21 211.84,155.19 204.98,155.19 C71.1 203.96,155.19 203.45,155.7 200.41,155.7 199.9,156.21 193.29,156.21 193.17,156.08 | R15.2 205.23,139.7 204.22,139.7 203.71,139.19 203.71,137.67 205.49,137.67 R14.2 | 193.17,156.08 192.28,155.19 C74.1 | C83.1 152.91,171.7 154.69,173.48 166.62,173.48 168.4,171.7 C80.1 169.42,171.7 170.43,172.72 178.82,172.72 179.83,171.7 C76.1 180.85,171.7 181.86,172.72 187.2,172.72 188.21,171.7 191.26,171.7 C73.1 192.28,171.7 192.53,171.96 198.12,171.96 198.88,172.72 205.74,172.72 205.87,172.59 | 219.84,172.59 218.95,171.7 C68.1 | 219.84,172.59 219.96,172.72 229.62,172.72 230.63,171.7 C65.1 | 205.87,172.59 205.99,172.72 219.71,172.72 219.84,172.59 | 205.87,172.59 204.98,171.7 C70.1 | 170.31,189.1 169.42,188.21 C79.1 | 170.31,189.1 170.43,189.23 178.82,189.23 179.83,188.21 C75.1 180.85,187.96 184.91,187.96 186.18,189.23 193.04,189.23 193.17,189.1 | C82.1 152.91,188.21 153.92,189.23 170.18,189.23 170.31,189.1 | U$12.A2 242.57,189.23 241.3,187.96 231.65,187.96 C64.1 230.63,188.21 229.62,189.23 219.96,189.23 219.84,189.1 | 219.84,189.1 218.95,188.21 C67.1 | 205.87,189.1 205.99,189.23 219.71,189.23 219.84,189.1 | 205.87,189.1 204.98,188.21 C69.1 | 193.17,189.1 193.29,189.23 205.74,189.23 205.87,189.1
  Bottom 0.381: 193.17,189.1 192.28,188.21 C72.1
VCC4
  Top 0.381: E105.4 152.65,82.8 153.42,82.8 153.42,87.63 152.65,88.39 C105.1 | E96.14 180.59,86.61 180.59,88.39 C98.1 | E102.14 169.16,86.61 169.16,88.39 C102.1 | E99.14 231.39,86.61 231.39,88.39 C87.1 230.89,89.41 230.12,90.17 230.12,102.36 230.89,103.12 E98.14 231.39,103.12 231.39,104.9 C86.1 | E86.14 218.69,86.61 218.69,88.39 C99.1 | C92.1 204.72,88.39 204.72,86.61 E90.14 205.99,86.36 206.5,85.85 206.5,74.68 205.99,74.17 R19.2 | E93.14 192.02,86.61 192.02,88.39 C95.1 | 151.77,105.03 151.89,105.16 C104.1 | 151.77,105.03 150.37,103.63 150.37,99.31 150.88,99.31 E104.4 | E95.14 180.59,103.12 180.59,104.9 C97.1 | E101.14 169.16,103.12 169.16,104.9 C101.1 | E92.14 192.02,103.12 192.02,104.9 C94.1 | E89.14 204.72,103.12 204.72,104.9 C91.1 | E87.14 218.69,103.12 218.69,104.9 C89.1 | C103.1 151.89,121.67 150.37,120.14 150.37,115.82 150.88,115.82 E103.4 150.88,115.57 149.61,114.3 149.61,107.19 151.64,105.16 151.77,105.03 | E94.14 180.59,119.63 180.59,121.41 C96.1 | E100.14 169.16,119.63 169.16,121.41 C100.1 | E91.14 192.02,119.63 192.02,121.41 C93.1 | E88.14 204.72,119.63 204.72,121.41 C90.1 | E85.14 218.69,119.63 218.69,121.41 C88.1 | E97.14 231.39,119.63 231.39,121.41 C85.1
  Bottom 0.381: 170.31,90.04 169.42,89.15 C102.1 | 170.31,90.04 170.43,90.17 178.82,90.17 179.83,89.15 C98.1 180.85,88.9 184.91,88.9 186.18,90.17 193.04,90.17 193.17,90.04 | C105.1 152.91,89.15 153.92,90.17 170.18,90.17 170.31,90.04 | C87.1 230.63,89.15 229.62,90.17 224.28,90.17 223.27,89.15 218.95,89.15 C99.1 217.93,89.15 216.92,90.17 212.85,90.17 211.84,89.15 204.98,89.15 C92.1 203.96,89.15 203.45,89.66 200.41,89.66 199.9,90.17 193.29,90.17 193.17,90.04 | R19.2 205.23,73.66 204.22,73.66 203.71,73.15 203.71,71.63 205.49,71.63 R18.2 | 193.17,90.04 192.28,89.15 C95.1 | C104.1 152.91,105.66 154.69,107.44 166.62,107.44 168.4,105.66 C101.1 169.42,105.66 170.43,106.68 178.82,106.68 179.83,105.66 C97.1 180.85,105.66 181.86,106.68 187.2,106.68 188.21,105.66 191.26,105.66 C94.1 192.28,105.66 192.53,105.92 198.12,105.92 198.88,106.68 205.74,106.68 205.87,106.55 | 219.84,106.55 218.95,105.66 C89.1 | 219.84,106.55 219.96,106.68 229.62,106.68 230.63,105.66 C86.1 | 205.87,106.55 205.99,106.68 219.71,106.68 219.84,106.55 | 205.87,106.55 204.98,105.66 C91.1 | 170.31,123.06 169.42,122.17 C100.1 | 170.31,123.06 170.43,123.19 178.82,123.19 179.83,122.17 C96.1 180.85,121.92 184.91,121.92 186.18,123.19 193.04,123.19 193.17,123.06 | C103.1 152.91,122.17 153.92,123.19 170.18,123.19 170.31,123.06 | U$15.A2 242.57,123.19 241.3,121.92 231.65,121.92 C85.1 230.63,122.17 229.62,123.19 219.96,123.19 219.84,123.06 | 219.84,123.06 218.95,122.17 C88.1 | 205.87,123.06 205.99,123.19 219.71,123.19 219.84,123.06 | 205.87,123.06 204.98,122.17 C90.1 | 193.17,123.06 193.29,123.19 205.74,123.19 205.87,123.06
  Bottom 0.381: 193.17,123.06 192.28,122.17 C93.1
VCC5
  Top 0.381: E126.4 152.65,16.76 153.42,16.76 153.42,21.59 152.65,22.35 C126.1 | E117.14 180.59,20.57 180.59,22.35 C119.1 | E123.14 169.16,20.57 169.16,22.35 C123.1 | E120.14 231.39,20.57 231.39,22.35 C108.1 230.89,23.37 230.12,24.13 230.12,36.32 230.89,37.08 E119.14 231.39,37.08 231.39,38.86 C107.1 | E107.14 218.69,20.57 218.69,22.35 C120.1 | C113.1 204.72,22.35 204.72,20.57 E111.14 205.99,20.32 206.5,19.81 206.5,8.64 205.99,8.13 R23.2 | E114.14 192.02,20.57 192.02,22.35 C116.1 | 151.77,38.99 151.89,39.12 C125.1 | 151.77,38.99 150.37,37.59 150.37,33.27 150.88,33.27 E125.4 | E116.14 180.59,37.08 180.59,38.86 C118.1 | E122.14 169.16,37.08 169.16,38.86 C122.1 | E113.14 192.02,37.08 192.02,38.86 C115.1 | E110.14 204.72,37.08 204.72,38.86 C112.1 | E108.14 218.69,37.08 218.69,38.86 C110.1 | C124.1 151.89,55.63 150.37,54.1 150.37,49.78 150.88,49.78 E124.4 150.88,49.53 149.61,48.26 149.61,41.15 151.64,39.12 151.77,38.99 | E115.14 180.59,53.59 180.59,55.37 C117.1 | E121.14 169.16,53.59 169.16,55.37 C121.1 | E112.14 192.02,53.59 192.02,55.37 C114.1 | E109.14 204.72,53.59 204.72,55.37 C111.1 | E106.14 218.69,53.59 218.69,55.37 C109.1 | E118.14 231.39,53.59 231.39,55.37 C106.1
  Bottom 0.381: 170.31,24 169.42,23.11 C123.1 | 170.31,24 170.43,24.13 178.82,24.13 179.83,23.11 C119.1 180.85,22.86 184.91,22.86 186.18,24.13 193.04,24.13 193.17,24 | C126.1 152.91,23.11 153.92,24.13 170.18,24.13 170.31,24 | C108.1 230.63,23.11 229.62,24.13 224.28,24.13 223.27,23.11 218.95,23.11 C120.1 217.93,23.11 216.92,24.13 212.85,24.13 211.84,23.11 204.98,23.11 C113.1 203.96,23.11 203.45,23.62 200.41,23.62 199.9,24.13 193.29,24.13 193.17,24 | R23.2 205.23,7.62 204.22,7.62 203.71,7.11 203.71,5.59 205.49,5.59 R22.2 | 193.17,24 192.28,23.11 C116.1 | C125.1 152.91,39.62 154.69,41.4 166.62,41.4 168.4,39.62 C122.1 169.42,39.62 170.43,40.64 178.82,40.64 179.83,39.62 C118.1 180.85,39.62 181.86,40.64 187.2,40.64 188.21,39.62 191.26,39.62 C115.1 192.28,39.62 192.53,39.88 198.12,39.88 198.88,40.64 205.74,40.64 205.87,40.51 | 219.84,40.51 218.95,39.62 C110.1 | 219.84,40.51 219.96,40.64 229.62,40.64 230.63,39.62 C107.1 | 205.87,40.51 205.99,40.64 219.71,40.64 219.84,40.51 | 205.87,40.51 204.98,39.62 C112.1 | 170.31,57.02 169.42,56.13 C121.1 | 170.31,57.02 170.43,57.15 178.82,57.15 179.83,56.13 C117.1 180.85,55.88 184.91,55.88 186.18,57.15 193.04,57.15 193.17,57.02 | C124.1 152.91,56.13 153.92,57.15 170.18,57.15 170.31,57.02 | U$18.A2 242.57,57.15 241.3,55.88 231.65,55.88 C106.1 230.63,56.13 229.62,57.15 219.96,57.15 219.84,57.02 | 219.84,57.02 218.95,56.13 C109.1 | 205.87,57.02 205.99,57.15 219.71,57.15 219.84,57.02 | 205.87,57.02 204.98,56.13 C111.1 | 193.17,57.02 193.29,57.15 205.74,57.15 205.87,57.02 | 193.17,57.02 192.28,56.13 C114.1

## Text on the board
Bottom: M111/M113/M115/M117/M119/M206/M209 | VRS | VRS | M111/M113/M115/M117/M119/M206/M209 | M111/M113/M115/M117/M119/M206/M209 | VRS | VRS | M111/M113/M115/M117/M119/M206/M209 | M111/M113/M115/M117/M119/M206/M209 | VRS | VRS | M111/M113/M115/M117/M119/M206/M209
tNames: M111/M113/M115/M117/M119/M206/M207 | M111/M115/M206/M207: Remove Resistors. | Fill Only One Row. | M113/M117/M119: | M119 | M117 | M115 | M113 | M111 | M111 | M113 | M115 | M117 | M119 | M113/M117/M119: | Fill Only One Row. | M111/M115/M206/M207: Remove Resistors. | M111/M113/M115/M117/M119/M206/M207 | M111/M113/M115/M117/M119/M206/M207 | M111/M115/M206/M207: Remove Resistors. | Fill Only One Row. | M113/M117/M119: | M119 | M117 | M115 | M113 | M111 | M111 | M113 | M115 | M117 | M119 | M113/M117/M119: | Fill Only One Row. | M111/M115/M206/M207: Remove Resistors. | M111/M113/M115/M117/M119/M206/M207 | M111/M113/M115/M117/M119/M206/M207 | M111/M115/M206/M207: Remove Resistors. | Fill Only One Row. | M113/M117/M119: | M119 | M117 | M115 | M113 | M111 | M111 | M113 | M115 | M117 | M119 | M113/M117/M119: | Fill Only One Row. | M111/M115/M206/M207: Remove Resistors. | M111/M113/M115/M117/M119/M206/M207
tValues: A1 | Add Resistors. | K2 | A1 | K2 | M206/M216 | M207 | M207 | M206/M216 | K2 | A1 | K2 | Add Resistors. | A1 | A1 | Add Resistors. | K2 | A1 | K2 | M206/M216 | M207 | M207 | M206/M216 | K2 | A1 | K2 | Add Resistors. | A1 | A1 | Add Resistors. | K2 | A1 | K2 | M206/M216 | M207 | M207 | M206/M216 | K2 | A1 | K2 | Add Resistors. | A1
